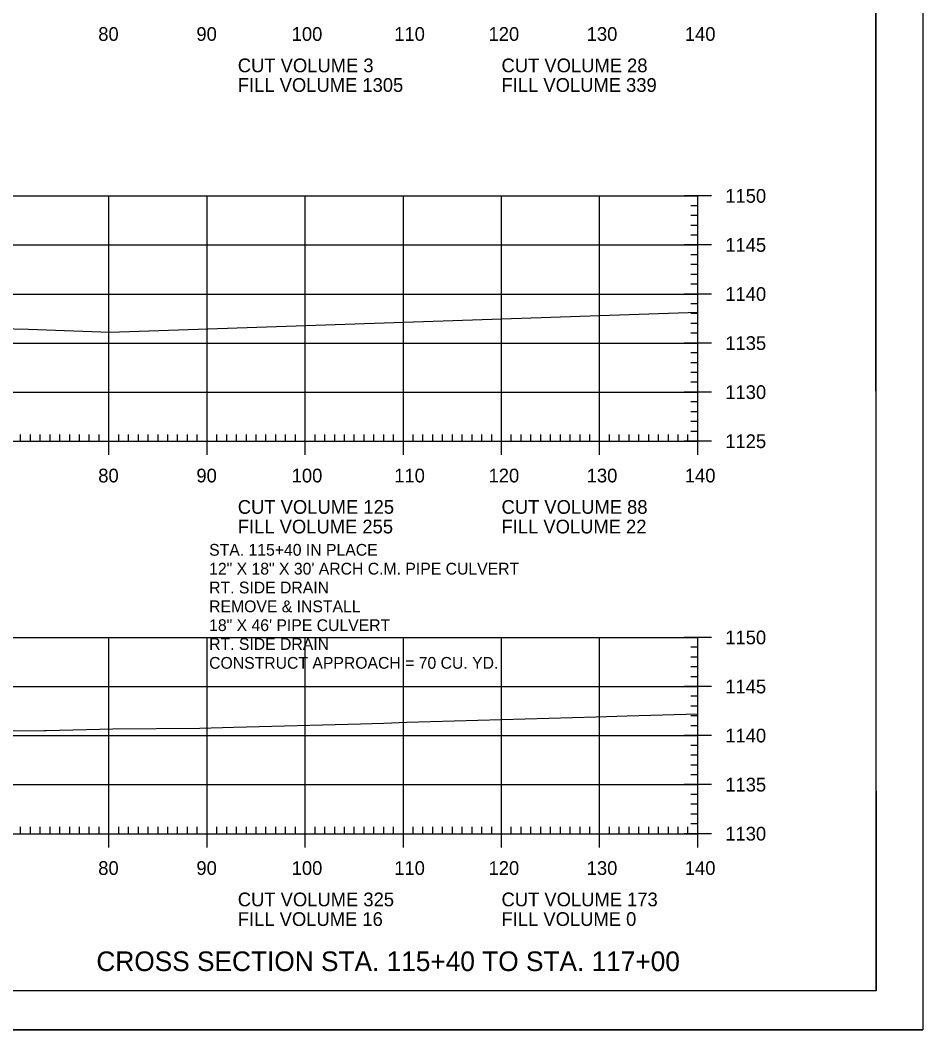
# Model space of a CAD drawing. Extents: x 1322838 to 1324533, y 339903 to 351025.
# Drawn here: x 1323774.7 to 1323866.6, y 340543.1 to 340646 of the extents above; entities that cross this region are included whole.
import ezdxf

# ---------------------------------------------------------------- set-up
doc = ezdxf.new("R2010")
doc.units = 0
for name, color, linetype in [('R_Axis', 7, 'Continuous'), ('R_Axis Annot', 7, 'Continuous'), ('R_Border', 7, 'Continuous'), ('R_Border Notes', 7, 'Continuous'), ('R_Draft', 7, 'Continuous'), ('R_Exist Surface', 7, 'Continuous'), ('R_Grid', 7, 'Continuous'), ('R_No Plot', 7, 'Continuous')]:
    doc.layers.add(name, color=color, linetype=linetype)

msp = doc.modelspace()

# ---------------------------------------------------------------- linework, layer by layer
at = {"layer": 'R_Axis'}
for p, q in [((1323845.12, 340628.12), (1323842.32, 340628.12)), ((1323843.72, 340603.12), (1323843.72, 340628.12)), ((1323843.72, 340627.12), (1323843.02, 340627.12)), ((1323843.72, 340626.12), (1323843.02, 340626.12)), ((1323843.72, 340625.12), (1323843.02, 340625.12)), ((1323843.72, 340624.12), (1323843.02, 340624.12)), ((1323845.12, 340623.12), (1323842.32, 340623.12)), ((1323843.72, 340622.12), (1323843.02, 340622.12)), ((1323843.72, 340621.12), (1323843.02, 340621.12)), ((1323843.72, 340620.12), (1323843.02, 340620.12)), ((1323843.72, 340619.12), (1323843.02, 340619.12)), ((1323845.12, 340618.12), (1323842.32, 340618.12)), ((1323843.72, 340617.12), (1323843.02, 340617.12)), ((1323843.72, 340616.12), (1323843.02, 340616.12)), ((1323843.72, 340615.12), (1323843.02, 340615.12)), ((1323843.72, 340614.12), (1323843.02, 340614.12)), ((1323845.12, 340613.12), (1323842.32, 340613.12)), ((1323843.72, 340612.12), (1323843.02, 340612.12)), ((1323843.72, 340611.12), (1323843.02, 340611.12)), ((1323843.72, 340610.12), (1323843.02, 340610.12)), ((1323843.72, 340609.12), (1323843.02, 340609.12)), ((1323845.12, 340608.12), (1323842.32, 340608.12)), ((1323843.72, 340607.12), (1323843.02, 340607.12)), ((1323843.72, 340606.12), (1323843.02, 340606.12)), ((1323843.72, 340605.12), (1323843.02, 340605.12)), ((1323783.72, 340601.72), (1323783.72, 340604.52)), ((1323793.72, 340601.72), (1323793.72, 340604.52)), ((1323803.72, 340601.72), (1323803.72, 340604.52)), ((1323813.72, 340601.72), (1323813.72, 340604.52)), ((1323823.72, 340601.72), (1323823.72, 340604.52)), ((1323833.72, 340601.72), (1323833.72, 340604.52)), ((1323843.72, 340604.12), (1323843.02, 340604.12)), ((1323843.72, 340601.72), (1323843.72, 340604.52)), ((1323563.72, 340603.12), (1323843.72, 340603.12)), ((1323774.72, 340603.12), (1323774.72, 340603.82)), ((1323775.72, 340603.12), (1323775.72, 340603.82)), ((1323776.72, 340603.12), (1323776.72, 340603.82)), ((1323777.72, 340603.12), (1323777.72, 340603.82)), ((1323778.72, 340603.12), (1323778.72, 340603.82)), ((1323779.72, 340603.12), (1323779.72, 340603.82)), ((1323780.72, 340603.12), (1323780.72, 340603.82)), ((1323781.72, 340603.12), (1323781.72, 340603.82)), ((1323782.72, 340603.12), (1323782.72, 340603.82)), ((1323784.72, 340603.12), (1323784.72, 340603.82)), ((1323785.72, 340603.12), (1323785.72, 340603.82)), ((1323786.72, 340603.12), (1323786.72, 340603.82)), ((1323787.72, 340603.12), (1323787.72, 340603.82)), ((1323788.72, 340603.12), (1323788.72, 340603.82)), ((1323789.72, 340603.12), (1323789.72, 340603.82)), ((1323790.72, 340603.12), (1323790.72, 340603.82)), ((1323791.72, 340603.12), (1323791.72, 340603.82)), ((1323792.72, 340603.12), (1323792.72, 340603.82)), ((1323794.72, 340603.12), (1323794.72, 340603.82)), ((1323795.72, 340603.12), (1323795.72, 340603.82)), ((1323796.72, 340603.12), (1323796.72, 340603.82)), ((1323797.72, 340603.12), (1323797.72, 340603.82)), ((1323798.72, 340603.12), (1323798.72, 340603.82)), ((1323799.72, 340603.12), (1323799.72, 340603.82)), ((1323800.72, 340603.12), (1323800.72, 340603.82)), ((1323801.72, 340603.12), (1323801.72, 340603.82)), ((1323802.72, 340603.12), (1323802.72, 340603.82)), ((1323804.72, 340603.12), (1323804.72, 340603.82)), ((1323805.72, 340603.12), (1323805.72, 340603.82)), ((1323806.72, 340603.12), (1323806.72, 340603.82)), ((1323807.72, 340603.12), (1323807.72, 340603.82)), ((1323808.72, 340603.12), (1323808.72, 340603.82)), ((1323809.72, 340603.12), (1323809.72, 340603.82)), ((1323810.72, 340603.12), (1323810.72, 340603.82)), ((1323811.72, 340603.12), (1323811.72, 340603.82)), ((1323812.72, 340603.12), (1323812.72, 340603.82)), ((1323814.72, 340603.12), (1323814.72, 340603.82)), ((1323815.72, 340603.12), (1323815.72, 340603.82)), ((1323816.72, 340603.12), (1323816.72, 340603.82)), ((1323817.72, 340603.12), (1323817.72, 340603.82)), ((1323818.72, 340603.12), (1323818.72, 340603.82)), ((1323819.72, 340603.12), (1323819.72, 340603.82)), ((1323820.72, 340603.12), (1323820.72, 340603.82)), ((1323821.72, 340603.12), (1323821.72, 340603.82)), ((1323822.72, 340603.12), (1323822.72, 340603.82)), ((1323824.72, 340603.12), (1323824.72, 340603.82)), ((1323825.72, 340603.12), (1323825.72, 340603.82)), ((1323826.72, 340603.12), (1323826.72, 340603.82)), ((1323827.72, 340603.12), (1323827.72, 340603.82)), ((1323828.72, 340603.12), (1323828.72, 340603.82)), ((1323829.72, 340603.12), (1323829.72, 340603.82)), ((1323830.72, 340603.12), (1323830.72, 340603.82)), ((1323831.72, 340603.12), (1323831.72, 340603.82)), ((1323832.72, 340603.12), (1323832.72, 340603.82)), ((1323834.72, 340603.12), (1323834.72, 340603.82)), ((1323835.72, 340603.12), (1323835.72, 340603.82)), ((1323836.72, 340603.12), (1323836.72, 340603.82)), ((1323837.72, 340603.12), (1323837.72, 340603.82)), ((1323838.72, 340603.12), (1323838.72, 340603.82)), ((1323839.72, 340603.12), (1323839.72, 340603.82)), ((1323840.72, 340603.12), (1323840.72, 340603.82)), ((1323841.72, 340603.12), (1323841.72, 340603.82)), ((1323845.12, 340603.12), (1323842.32, 340603.12)), ((1323842.72, 340603.12), (1323842.72, 340603.82)), ((1323845.12, 340583.12), (1323842.32, 340583.12)), ((1323843.72, 340563.12), (1323843.72, 340583.12)), ((1323843.72, 340582.12), (1323843.02, 340582.12)), ((1323843.72, 340581.12), (1323843.02, 340581.12)), ((1323843.72, 340580.12), (1323843.02, 340580.12)), ((1323845.12, 340578.12), (1323842.32, 340578.12)), ((1323843.72, 340579.12), (1323843.02, 340579.12)), ((1323843.72, 340577.12), (1323843.02, 340577.12)), ((1323843.72, 340576.12), (1323843.02, 340576.12)), ((1323843.72, 340575.12), (1323843.02, 340575.12)), ((1323843.72, 340574.12), (1323843.02, 340574.12)), ((1323845.12, 340573.12), (1323842.32, 340573.12)), ((1323843.72, 340572.12), (1323843.02, 340572.12)), ((1323843.72, 340571.12), (1323843.02, 340571.12)), ((1323843.72, 340570.12), (1323843.02, 340570.12)), ((1323843.72, 340569.12), (1323843.02, 340569.12)), ((1323845.12, 340568.12), (1323842.32, 340568.12)), ((1323843.72, 340567.12), (1323843.02, 340567.12)), ((1323843.72, 340566.12), (1323843.02, 340566.12)), ((1323843.72, 340565.12), (1323843.02, 340565.12)), ((1323774.72, 340563.12), (1323774.72, 340563.82)), ((1323775.72, 340563.12), (1323775.72, 340563.82)), ((1323776.72, 340563.12), (1323776.72, 340563.82)), ((1323777.72, 340563.12), (1323777.72, 340563.82)), ((1323778.72, 340563.12), (1323778.72, 340563.82)), ((1323779.72, 340563.12), (1323779.72, 340563.82)), ((1323780.72, 340563.12), (1323780.72, 340563.82)), ((1323781.72, 340563.12), (1323781.72, 340563.82)), ((1323782.72, 340563.12), (1323782.72, 340563.82)), ((1323783.72, 340561.72), (1323783.72, 340564.52)), ((1323784.72, 340563.12), (1323784.72, 340563.82)), ((1323785.72, 340563.12), (1323785.72, 340563.82)), ((1323786.72, 340563.12), (1323786.72, 340563.82)), ((1323787.72, 340563.12), (1323787.72, 340563.82)), ((1323788.72, 340563.12), (1323788.72, 340563.82)), ((1323789.72, 340563.12), (1323789.72, 340563.82)), ((1323790.72, 340563.12), (1323790.72, 340563.82)), ((1323791.72, 340563.12), (1323791.72, 340563.82)), ((1323792.72, 340563.12), (1323792.72, 340563.82)), ((1323793.72, 340561.72), (1323793.72, 340564.52)), ((1323794.72, 340563.12), (1323794.72, 340563.82)), ((1323795.72, 340563.12), (1323795.72, 340563.82)), ((1323796.72, 340563.12), (1323796.72, 340563.82)), ((1323797.72, 340563.12), (1323797.72, 340563.82)), ((1323798.72, 340563.12), (1323798.72, 340563.82)), ((1323799.72, 340563.12), (1323799.72, 340563.82)), ((1323800.72, 340563.12), (1323800.72, 340563.82)), ((1323801.72, 340563.12), (1323801.72, 340563.82)), ((1323802.72, 340563.12), (1323802.72, 340563.82)), ((1323803.72, 340561.72), (1323803.72, 340564.52)), ((1323804.72, 340563.12), (1323804.72, 340563.82)), ((1323805.72, 340563.12), (1323805.72, 340563.82)), ((1323806.72, 340563.12), (1323806.72, 340563.82)), ((1323807.72, 340563.12), (1323807.72, 340563.82)), ((1323808.72, 340563.12), (1323808.72, 340563.82)), ((1323809.72, 340563.12), (1323809.72, 340563.82)), ((1323810.72, 340563.12), (1323810.72, 340563.82)), ((1323811.72, 340563.12), (1323811.72, 340563.82)), ((1323812.72, 340563.12), (1323812.72, 340563.82)), ((1323813.72, 340561.72), (1323813.72, 340564.52)), ((1323814.72, 340563.12), (1323814.72, 340563.82)), ((1323815.72, 340563.12), (1323815.72, 340563.82)), ((1323816.72, 340563.12), (1323816.72, 340563.82)), ((1323817.72, 340563.12), (1323817.72, 340563.82)), ((1323818.72, 340563.12), (1323818.72, 340563.82)), ((1323819.72, 340563.12), (1323819.72, 340563.82)), ((1323820.72, 340563.12), (1323820.72, 340563.82)), ((1323821.72, 340563.12), (1323821.72, 340563.82)), ((1323822.72, 340563.12), (1323822.72, 340563.82)), ((1323823.72, 340561.72), (1323823.72, 340564.52)), ((1323824.72, 340563.12), (1323824.72, 340563.82)), ((1323825.72, 340563.12), (1323825.72, 340563.82)), ((1323826.72, 340563.12), (1323826.72, 340563.82)), ((1323827.72, 340563.12), (1323827.72, 340563.82)), ((1323828.72, 340563.12), (1323828.72, 340563.82)), ((1323829.72, 340563.12), (1323829.72, 340563.82)), ((1323830.72, 340563.12), (1323830.72, 340563.82)), ((1323831.72, 340563.12), (1323831.72, 340563.82)), ((1323832.72, 340563.12), (1323832.72, 340563.82)), ((1323833.72, 340561.72), (1323833.72, 340564.52)), ((1323834.72, 340563.12), (1323834.72, 340563.82)), ((1323835.72, 340563.12), (1323835.72, 340563.82)), ((1323836.72, 340563.12), (1323836.72, 340563.82)), ((1323837.72, 340563.12), (1323837.72, 340563.82)), ((1323838.72, 340563.12), (1323838.72, 340563.82)), ((1323839.72, 340563.12), (1323839.72, 340563.82)), ((1323840.72, 340563.12), (1323840.72, 340563.82)), ((1323841.72, 340563.12), (1323841.72, 340563.82)), ((1323842.72, 340563.12), (1323842.72, 340563.82)), ((1323843.72, 340564.12), (1323843.02, 340564.12)), ((1323843.72, 340561.72), (1323843.72, 340564.52)), ((1323563.72, 340563.12), (1323843.72, 340563.12)), ((1323845.12, 340563.12), (1323842.32, 340563.12))]:
    msp.add_line(p, q, dxfattribs=at)
at = {"layer": 'R_Border'}
for q in [(1323861.9, 340752.58), (1323545.72, 340547.12)]:
    msp.add_line((1323861.9, 340547.12), q, dxfattribs=at)
at = {"layer": 'R_Exist Surface'}
for points in [[(1323763.95, 340614.82), (1323775.51, 340614.54), (1323783.81, 340614.23), (1323843.72, 340616.26)], [(1323772.19, 340573.6), (1323777.14, 340573.63), (1323777.33, 340573.65), (1323784.13, 340573.82), (1323792.97, 340573.86), (1323796.43, 340573.96), (1323809.35, 340574.33), (1323811.73, 340574.4), (1323814.09, 340574.47), (1323833.35, 340575.04), (1323836.51, 340575.12), (1323843.72, 340575.34)]]:
    msp.add_lwpolyline(points, dxfattribs=at)
at = {"layer": 'R_Grid'}
for p, q in [((1323563.72, 340628.12), (1323843.72, 340628.12)), ((1323783.72, 340603.12), (1323783.72, 340628.12)), ((1323793.72, 340603.12), (1323793.72, 340628.12)), ((1323803.72, 340603.12), (1323803.72, 340628.12)), ((1323813.72, 340603.12), (1323813.72, 340628.12)), ((1323823.72, 340603.12), (1323823.72, 340628.12)), ((1323833.72, 340603.12), (1323833.72, 340628.12)), ((1323843.72, 340603.12), (1323843.72, 340628.12)), ((1323563.72, 340623.12), (1323843.72, 340623.12)), ((1323563.72, 340618.12), (1323843.72, 340618.12)), ((1323563.72, 340613.12), (1323843.72, 340613.12)), ((1323563.72, 340608.12), (1323843.72, 340608.12)), ((1323563.72, 340603.12), (1323843.72, 340603.12)), ((1323563.72, 340583.12), (1323843.72, 340583.12)), ((1323783.72, 340563.12), (1323783.72, 340583.12)), ((1323793.72, 340563.12), (1323793.72, 340583.12)), ((1323803.72, 340563.12), (1323803.72, 340583.12)), ((1323813.72, 340563.12), (1323813.72, 340583.12)), ((1323823.72, 340563.12), (1323823.72, 340583.12)), ((1323833.72, 340563.12), (1323833.72, 340583.12)), ((1323843.72, 340563.12), (1323843.72, 340583.12)), ((1323563.72, 340578.12), (1323843.72, 340578.12)), ((1323563.72, 340573.12), (1323843.72, 340573.12)), ((1323563.72, 340568.12), (1323843.72, 340568.12)), ((1323563.72, 340563.12), (1323843.72, 340563.12))]:
    msp.add_line(p, q, dxfattribs=at)
at = {"layer": 'R_No Plot'}
msp.add_line((1323533.31, 340543.14), (1323866.65, 340543.14), dxfattribs=at)
for points in [[(1323533.31, 340756.47), (1323866.65, 340756.47), (1323866.65, 340543.13), (1323533.31, 340543.13)], [(1323779.64, 340752.58), (1323799.26, 340752.58), (1323799.26, 340742.7), (1323815.37, 340742.7), (1323838.57, 340742.7), (1323838.57, 340710.03), (1323861.77, 340710.03), (1323861.9, 340547.12), (1323545.72, 340547.12), (1323545.72, 340752.58)]]:
    msp.add_lwpolyline(points, close=True, dxfattribs=at)

# ---------------------------------------------------------------- texts
at = {"layer": 'R_Axis Annot'}
for s, p in [('80', (1323782.63, 340643.92)), ('90', (1323792.63, 340643.92)), ('100', (1323802.34, 340643.92)), ('110', (1323812.79, 340643.92)), ('120', (1323822.4, 340643.92)), ('130', (1323832.4, 340643.92)), ('140', (1323842.4, 340643.92)), ('CUT VOLUME 3', (1323796.85, 340640.72)), ('CUT VOLUME 28', (1323823.72, 340640.72)), ('FILL VOLUME 1305', (1323796.85, 340638.72)), ('FILL VOLUME 339', (1323823.72, 340638.72)), ('1150', (1323846.52, 340627.42)), ('1145', (1323846.52, 340622.42)), ('1140', (1323846.52, 340617.42)), ('1135', (1323846.52, 340612.42)), ('1130', (1323846.52, 340607.42)), ('1125', (1323846.52, 340602.42)), ('80', (1323782.63, 340598.92)), ('90', (1323792.63, 340598.92)), ('100', (1323802.34, 340598.92)), ('110', (1323812.79, 340598.92)), ('120', (1323822.4, 340598.92)), ('130', (1323832.4, 340598.92)), ('140', (1323842.4, 340598.92)), ('CUT VOLUME 125', (1323796.85, 340595.72)), ('CUT VOLUME 88', (1323823.72, 340595.72)), ('FILL VOLUME 255', (1323796.85, 340593.72)), ('FILL VOLUME 22', (1323823.72, 340593.72)), ('1150', (1323846.52, 340582.42)), ('1145', (1323846.52, 340577.42)), ('1140', (1323846.52, 340572.42)), ('1135', (1323846.52, 340567.42)), ('1130', (1323846.52, 340562.42)), ('80', (1323782.63, 340558.92)), ('90', (1323792.63, 340558.92)), ('100', (1323802.34, 340558.92)), ('110', (1323812.79, 340558.92)), ('120', (1323822.4, 340558.92)), ('130', (1323832.4, 340558.92)), ('140', (1323842.4, 340558.92)), ('CUT VOLUME 325', (1323796.85, 340555.72)), ('CUT VOLUME 173', (1323823.72, 340555.72)), ('FILL VOLUME 16', (1323796.85, 340553.72)), ('FILL VOLUME 0', (1323823.72, 340553.72))]:
    msp.add_text(s, height=1.4, dxfattribs=at).set_placement(p)
at = {"layer": 'R_Border Notes'}
for s, p in [('STA. 115+40 IN PLACE', (1323793.93, 340591.45)), ('12" X 18" X 30\' ARCH C.M. PIPE CULVERT', (1323793.93, 340589.53)), ('RT. SIDE DRAIN', (1323793.93, 340587.61)), ('REMOVE & INSTALL', (1323793.93, 340585.69)), ('18" X 46\' PIPE CULVERT', (1323793.93, 340583.77)), ('RT. SIDE DRAIN', (1323793.93, 340581.85)), ('CONSTRUCT APPROACH = 70 CU. YD.', (1323793.93, 340579.93))]:
    msp.add_text(s, height=1.2, dxfattribs=at).set_placement(p)
at = {"layer": 'R_Draft'}
msp.add_text('CROSS SECTION STA. 115+40 TO STA. 117+00', height=2, dxfattribs=at).set_placement((1323782.44, 340549.12))

doc.saveas('drawing.dxf')
